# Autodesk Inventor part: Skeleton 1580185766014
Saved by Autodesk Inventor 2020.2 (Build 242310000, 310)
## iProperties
Created: 2020-01
Part Number: Skeleton 1580185766014
Material: Generic
Document SubType Name: Modeling
Designer: thira
Density: 1 g/cm^3
Appearance: Default
_SkeletonDoc: Frame Skeleton File
_Version: 15.0.0
Author: thira
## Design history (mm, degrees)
sketch "Reference Skeleton"
